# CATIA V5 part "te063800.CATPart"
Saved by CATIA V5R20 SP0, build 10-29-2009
Part number: 1
Definition: NONE
Nomenclature: 1
Source: Unknown
Description: PART-1-DESC
Bounding box of the stored display mesh (mm): x 0 to 800, y -3 to 3, z -2.853 to 2.853
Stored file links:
  C:\Users\Utente\Desktop\IO LAVORO\3D X SITO CF\CUMSA\3D files TE\te063800.CATPart
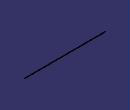
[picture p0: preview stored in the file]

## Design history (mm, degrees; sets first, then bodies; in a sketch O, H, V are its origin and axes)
Body1 "1" (main body)
  Solid1: solid without history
